(* Logix 5000 project; controller DNP3Outstation 1756-L62 rev 19.11; software revision 19.01; part 2 of 3 *)

ADD_ON_INSTRUCTION PSDNP3CounterControl16   (* revision 1.0, vendor ProSoft Technology Inc *)
// DNP3 Outstation Counter Control
VAR_IN_OUT
   Control : PSDNP3CounterCtrl; {required}
   Counter : INT; {required}
   FrozenCounter : INT; {required}
END_VAR
VAR_OUTPUT
   CurrentCountValue : DINT; {access Read Only, visible}
   FrozenCountValue : DINT; {access Read Only, visible}
   ClearRequestCount : DINT; {visible}
   FreezeRequestCount : DINT; {access Read Only, visible}
END_VAR
VAR_INPUT
   ResetStatistics : BOOL; {required}
END_VAR
VAR_OUTPUT
   FreezeAction : BOOL; {access Read Only, visible}
   ClearAction : BOOL; {access Read Only, visible}
END_VAR
VAR
   FreezeRequestCounter : COUNTER := (PRE := 2100000000); {access None}
   ClearRequestCounter : COUNTER := (PRE := 2100000000); {access None}
END_VAR

ROUTINE Logic   (* ladder *)
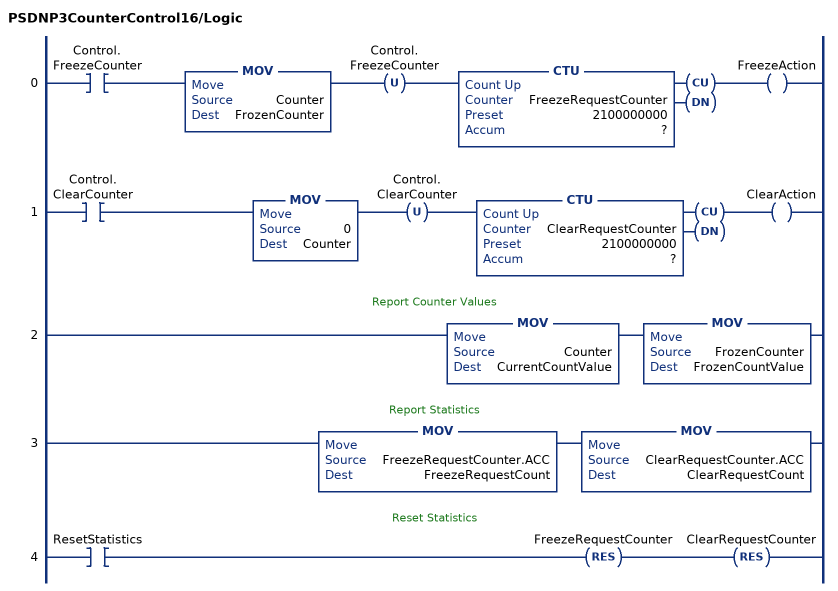
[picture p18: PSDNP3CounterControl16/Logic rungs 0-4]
   0: XIC(Control.FreezeCounter)MOV(Counter,FrozenCounter)OTU(Control.FreezeCounter)CTU(FreezeRequestCounter,?,?)OTE(FreezeAction);
   1: XIC(Control.ClearCounter)MOV(0,Counter)OTU(Control.ClearCounter)CTU(ClearRequestCounter,?,?)OTE(ClearAction);
   // Report Counter Values
   2: MOV(Counter,CurrentCountValue)MOV(FrozenCounter,FrozenCountValue);
   // Report Statistics
   3: MOV(FreezeRequestCounter.ACC,FreezeRequestCount)MOV(ClearRequestCounter.ACC,ClearRequestCount);
   // Reset Statistics
   4: XIC(ResetStatistics)RES(FreezeRequestCounter)RES(ClearRequestCounter);
END_ROUTINE
END_ADD_ON_INSTRUCTION

ADD_ON_INSTRUCTION PSDNP3CounterControl16Flag   (* revision 1.0, vendor ProSoft Technology Inc *)
// DNP3 Outstation Counter Control
VAR_IN_OUT
   Control : PSDNP3CounterCtrl; {required}
   Counter : PSDNP3Counter16WithFlag; {required}
   FrozenCounter : PSDNP3FrozenCounter16WithFlag; {required}
END_VAR
VAR_OUTPUT
   CurrentCountValue : DINT; {access Read Only, visible}
   FrozenCountValue : DINT; {access Read Only, visible}
   ClearRequestCount : DINT; {visible}
   FreezeRequestCount : DINT; {access Read Only, visible}
END_VAR
VAR_INPUT
   ResetStatistics : BOOL; {required}
END_VAR
VAR_OUTPUT
   FreezeAction : BOOL; {access Read Only, visible}
   ClearAction : BOOL; {access Read Only, visible}
END_VAR
VAR
   FreezeRequestCounter : COUNTER := (PRE := 2100000000); {access None}
   ClearRequestCounter : COUNTER := (PRE := 2100000000); {access None}
END_VAR

ROUTINE Logic   (* ladder *)
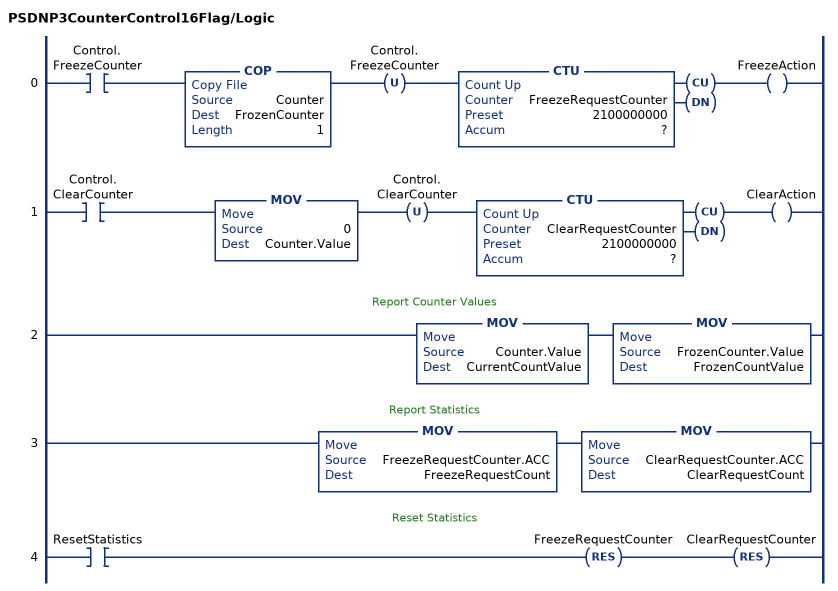
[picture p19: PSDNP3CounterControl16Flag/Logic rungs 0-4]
   0: XIC(Control.FreezeCounter)COP(Counter,FrozenCounter,1)OTU(Control.FreezeCounter)CTU(FreezeRequestCounter,?,?)OTE(FreezeAction);
   1: XIC(Control.ClearCounter)MOV(0,Counter.Value)OTU(Control.ClearCounter)CTU(ClearRequestCounter,?,?)OTE(ClearAction);
   // Report Counter Values
   2: MOV(Counter.Value,CurrentCountValue)MOV(FrozenCounter.Value,FrozenCountValue);
   // Report Statistics
   3: MOV(FreezeRequestCounter.ACC,FreezeRequestCount)MOV(ClearRequestCounter.ACC,ClearRequestCount);
   // Reset Statistics
   4: XIC(ResetStatistics)RES(FreezeRequestCounter)RES(ClearRequestCounter);
END_ROUTINE
END_ADD_ON_INSTRUCTION

ADD_ON_INSTRUCTION PSDNP3CounterControl16FlagTime   (* revision 1.0, vendor ProSoft Technology Inc *)
// DNP3 Outstation Counter Control
VAR_IN_OUT
   Control : PSDNP3CounterCtrl; {required}
   Counter : PSDNP3Counter16WithFlag; {required}
   FrozenCounter : PSDNP3FrozenCounter16WithFlagTimeRev2; {required}
END_VAR
VAR_OUTPUT
   CurrentCountValue : DINT; {access Read Only, visible}
   FrozenCountValue : DINT; {access Read Only, visible}
   ClearRequestCount : DINT; {visible}
   FreezeRequestCount : DINT; {access Read Only, visible}
END_VAR
VAR_INPUT
   ResetStatistics : BOOL; {required}
END_VAR
VAR_OUTPUT
   FreezeAction : BOOL; {access Read Only, visible}
   ClearAction : BOOL; {access Read Only, visible}
END_VAR
VAR
   FreezeRequestCounter : COUNTER := (PRE := 2100000000); {access None}
   ClearRequestCounter : COUNTER := (PRE := 2100000000); {access None}
END_VAR

ROUTINE Logic   (* ladder *)
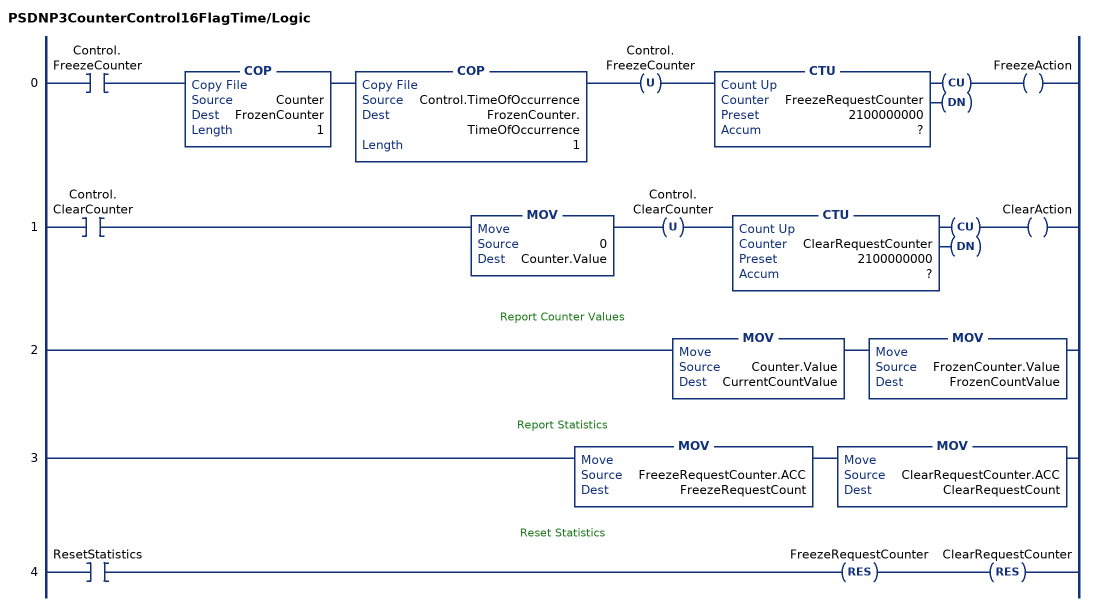
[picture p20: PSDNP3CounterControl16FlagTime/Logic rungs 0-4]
   0: XIC(Control.FreezeCounter)COP(Counter,FrozenCounter,1)COP(Control.TimeOfOccurrence,FrozenCounter.TimeOfOccurrence,1)OTU(Control.FreezeCounter)CTU(FreezeRequestCounter,?,?)OTE(FreezeAction);
   1: XIC(Control.ClearCounter)MOV(0,Counter.Value)OTU(Control.ClearCounter)CTU(ClearRequestCounter,?,?)OTE(ClearAction);
   // Report Counter Values
   2: MOV(Counter.Value,CurrentCountValue)MOV(FrozenCounter.Value,FrozenCountValue);
   // Report Statistics
   3: MOV(FreezeRequestCounter.ACC,FreezeRequestCount)MOV(ClearRequestCounter.ACC,ClearRequestCount);
   // Reset Statistics
   4: XIC(ResetStatistics)RES(FreezeRequestCounter)RES(ClearRequestCounter);
END_ROUTINE
END_ADD_ON_INSTRUCTION

ADD_ON_INSTRUCTION PSDNP3CounterControl32   (* revision 1.0, vendor ProSoft Technology Inc *)
// DNP3 Outstation Counter Control
VAR_IN_OUT
   Control : PSDNP3CounterCtrl; {required}
   Counter : DINT; {required}
   FrozenCounter : DINT; {required}
END_VAR
VAR_OUTPUT
   CurrentCountValue : DINT; {access Read Only, visible}
   FrozenCountValue : DINT; {access Read Only, visible}
   ClearRequestCount : DINT; {visible}
   FreezeRequestCount : DINT; {access Read Only, visible}
END_VAR
VAR_INPUT
   ResetStatistics : BOOL; {required}
END_VAR
VAR_OUTPUT
   FreezeAction : BOOL; {access Read Only, visible}
   ClearAction : BOOL; {access Read Only, visible}
END_VAR
VAR
   FreezeRequestCounter : COUNTER := (PRE := 2100000000); {access None}
   ClearRequestCounter : COUNTER := (PRE := 2100000000); {access None}
END_VAR

ROUTINE Logic   (* ladder *)
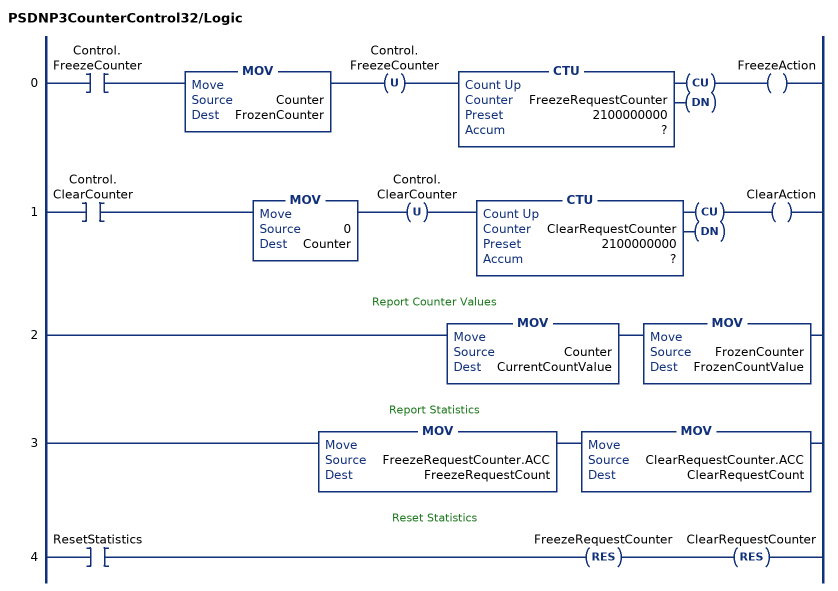
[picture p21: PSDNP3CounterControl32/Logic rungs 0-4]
   0: XIC(Control.FreezeCounter)MOV(Counter,FrozenCounter)OTU(Control.FreezeCounter)CTU(FreezeRequestCounter,?,?)OTE(FreezeAction);
   1: XIC(Control.ClearCounter)MOV(0,Counter)OTU(Control.ClearCounter)CTU(ClearRequestCounter,?,?)OTE(ClearAction);
   // Report Counter Values
   2: MOV(Counter,CurrentCountValue)MOV(FrozenCounter,FrozenCountValue);
   // Report Statistics
   3: MOV(FreezeRequestCounter.ACC,FreezeRequestCount)MOV(ClearRequestCounter.ACC,ClearRequestCount);
   // Reset Statistics
   4: XIC(ResetStatistics)RES(FreezeRequestCounter)RES(ClearRequestCounter);
END_ROUTINE
END_ADD_ON_INSTRUCTION

ADD_ON_INSTRUCTION PSDNP3CounterControl32Flag   (* revision 1.0, vendor ProSoft Technology Inc *)
// DNP3 Outstation Counter Control
VAR_IN_OUT
   Control : PSDNP3CounterCtrl; {required}
   Counter : PSDNP3Counter32WithFlag; {required}
   FrozenCounter : PSDNP3FrozenCounter32WithFlag; {required}
END_VAR
VAR_OUTPUT
   CurrentCountValue : DINT; {access Read Only, visible}
   FrozenCountValue : DINT; {access Read Only, visible}
   ClearRequestCount : DINT; {visible}
   FreezeRequestCount : DINT; {access Read Only, visible}
END_VAR
VAR_INPUT
   ResetStatistics : BOOL; {required}
END_VAR
VAR_OUTPUT
   FreezeAction : BOOL; {access Read Only, visible}
   ClearAction : BOOL; {access Read Only, visible}
END_VAR
VAR
   FreezeRequestCounter : COUNTER := (PRE := 2100000000); {access None}
   ClearRequestCounter : COUNTER := (PRE := 2100000000); {access None}
END_VAR

ROUTINE Logic   (* ladder *)
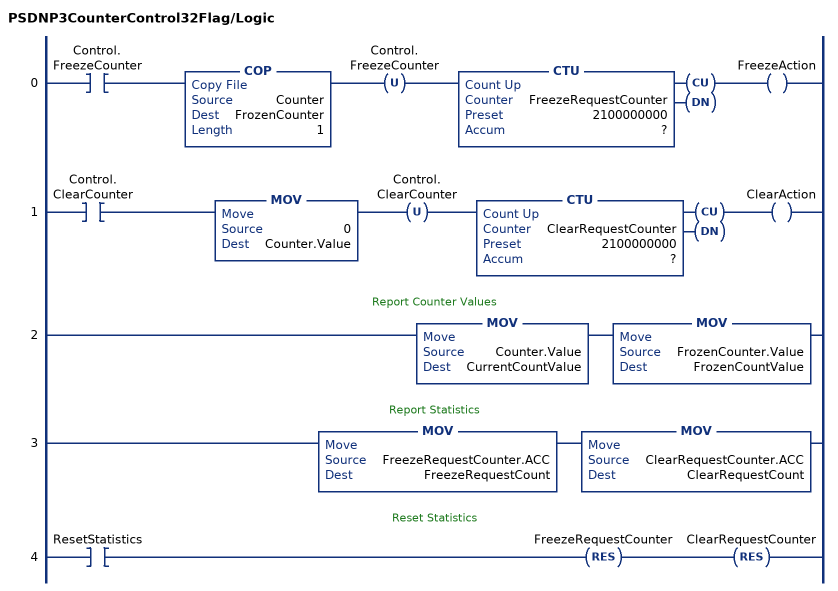
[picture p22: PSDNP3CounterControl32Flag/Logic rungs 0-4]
   0: XIC(Control.FreezeCounter)COP(Counter,FrozenCounter,1)OTU(Control.FreezeCounter)CTU(FreezeRequestCounter,?,?)OTE(FreezeAction);
   1: XIC(Control.ClearCounter)MOV(0,Counter.Value)OTU(Control.ClearCounter)CTU(ClearRequestCounter,?,?)OTE(ClearAction);
   // Report Counter Values
   2: MOV(Counter.Value,CurrentCountValue)MOV(FrozenCounter.Value,FrozenCountValue);
   // Report Statistics
   3: MOV(FreezeRequestCounter.ACC,FreezeRequestCount)MOV(ClearRequestCounter.ACC,ClearRequestCount);
   // Reset Statistics
   4: XIC(ResetStatistics)RES(FreezeRequestCounter)RES(ClearRequestCounter);
END_ROUTINE
END_ADD_ON_INSTRUCTION

ADD_ON_INSTRUCTION PSDNP3CounterControl32FlagTime   (* revision 1.0, vendor ProSoft Technology Inc *)
// DNP3 Outstation Counter Control
VAR_IN_OUT
   Control : PSDNP3CounterCtrl; {required}
   Counter : PSDNP3Counter32WithFlag; {required}
   FrozenCounter : PSDNP3FrozenCounter32WithFlagTime; {required}
END_VAR
VAR_OUTPUT
   CurrentCountValue : DINT; {access Read Only, visible}
   FrozenCountValue : DINT; {access Read Only, visible}
   ClearRequestCount : DINT; {visible}
   FreezeRequestCount : DINT; {access Read Only, visible}
END_VAR
VAR_INPUT
   ResetStatistics : BOOL; {required}
END_VAR
VAR_OUTPUT
   FreezeAction : BOOL; {access Read Only, visible}
   ClearAction : BOOL; {access Read Only, visible}
END_VAR
VAR
   FreezeRequestCounter : COUNTER; {access None}
   ClearRequestCounter : COUNTER; {access None}
END_VAR

ROUTINE Logic   (* ladder *)
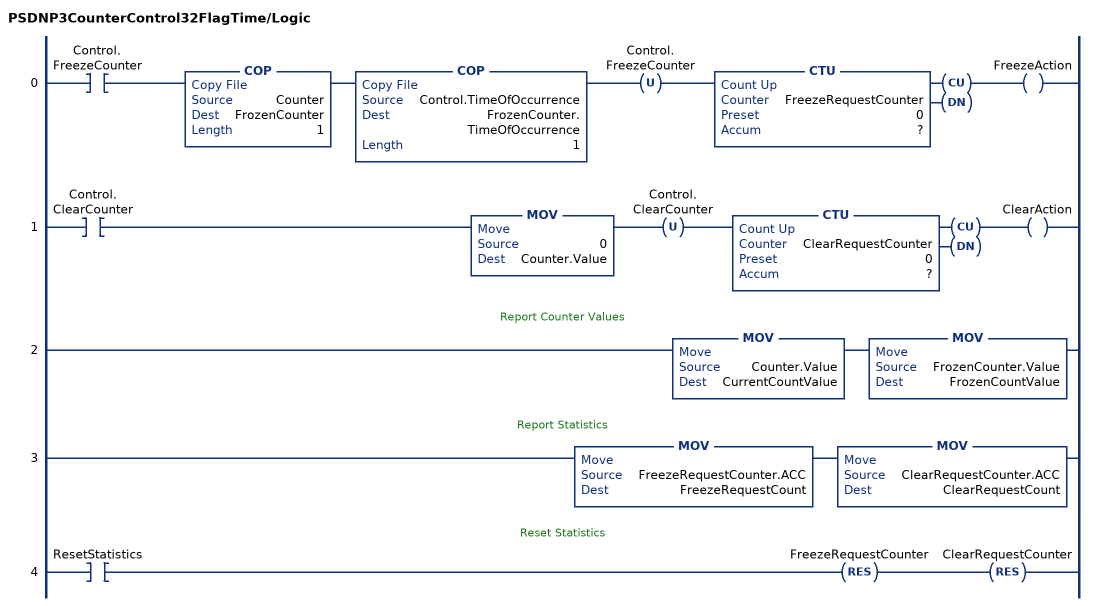
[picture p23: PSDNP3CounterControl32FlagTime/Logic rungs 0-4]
   0: XIC(Control.FreezeCounter)COP(Counter,FrozenCounter,1)COP(Control.TimeOfOccurrence,FrozenCounter.TimeOfOccurrence,1)OTU(Control.FreezeCounter)CTU(FreezeRequestCounter,?,?)OTE(FreezeAction);
   1: XIC(Control.ClearCounter)MOV(0,Counter.Value)OTU(Control.ClearCounter)CTU(ClearRequestCounter,?,?)OTE(ClearAction);
   // Report Counter Values
   2: MOV(Counter.Value,CurrentCountValue)MOV(FrozenCounter.Value,FrozenCountValue);
   // Report Statistics
   3: MOV(FreezeRequestCounter.ACC,FreezeRequestCount)MOV(ClearRequestCounter.ACC,ClearRequestCount);
   // Reset Statistics
   4: XIC(ResetStatistics)RES(FreezeRequestCounter)RES(ClearRequestCounter);
END_ROUTINE
END_ADD_ON_INSTRUCTION

ADD_ON_INSTRUCTION PSDNP3CounterEvtLog16   (* revision 1.0, vendor ProSoft Technology Inc *)
VAR_IN_OUT
   DNP3Object : PSDNP3Counter16WithFlag; {required}
END_VAR
VAR_INPUT
   Deadband : INT; {required}
   MinimumLogInterval : REAL; {required}
   ExtrernalEventTrigger : BOOL; {visible}
END_VAR
VAR_OUTPUT
   EventTriggers : DINT; {access Read Only, visible}
END_VAR
VAR
   RequestLog : BOOL; {access None}
   ExternalONS : BOOL; {access None}
   Interval : TIMER := (PRE := 1000000); {access None}
   PreviousValue : INT; {access None}
   DBRequest : BOOL; {access None}
   ExtRequest : BOOL; {access None}
   Pending : BOOL; {access None}
END_VAR

ROUTINE Logic   (* ladder *)
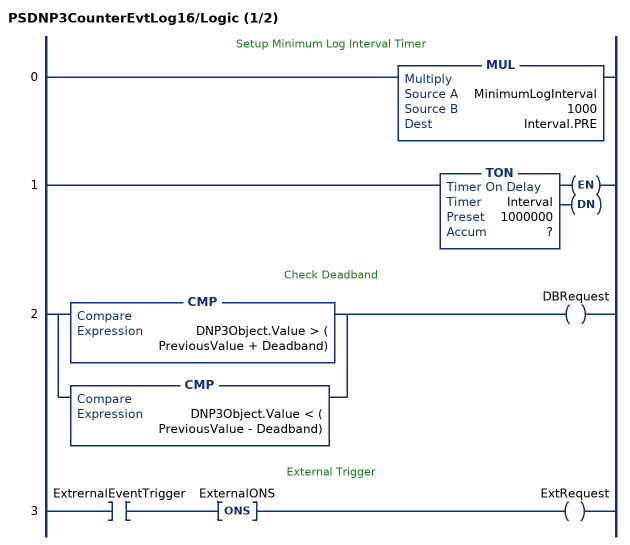
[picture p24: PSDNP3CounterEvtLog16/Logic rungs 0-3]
   // Setup Minimum Log Interval Timer
   0: MUL(MinimumLogInterval,1000,Interval.PRE);
   1: TON(Interval,?,?);
   // Check Deadband
   2: [CMP(DNP3Object.Value > ( PreviousValue + Deadband)) ,CMP(DNP3Object.Value < ( PreviousValue - Deadband)) ]OTE(DBRequest);
   // External Trigger
   3: XIC(ExtrernalEventTrigger)ONS(ExternalONS)OTE(ExtRequest);
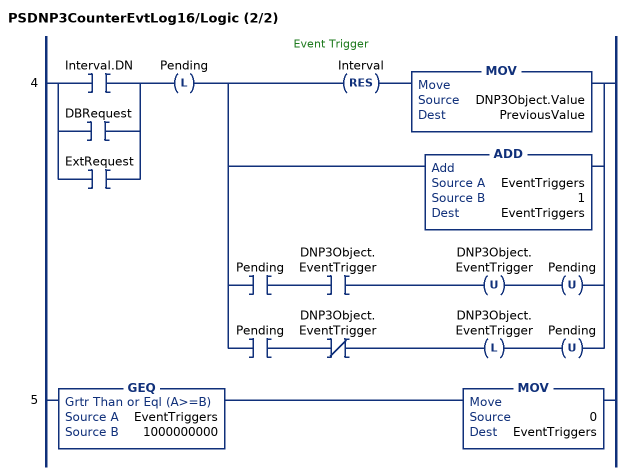
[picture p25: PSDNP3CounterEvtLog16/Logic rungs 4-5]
   // Event Trigger
   4: [XIC(Interval.DN) ,XIC(DBRequest) ,XIC(ExtRequest) ]OTL(Pending)[RES(Interval) MOV(DNP3Object.Value,PreviousValue) ,ADD(EventTriggers,1,EventTriggers) ,XIC(Pending) XIC(DNP3Object.EventTrigger) OTU(DNP3Object.EventTrigger) OTU(Pending) ,XIC(Pending) XIO(DNP3Object.EventTrigger) OTL(DNP3Object.EventTrigger) OTU(Pending) ];
   5: GEQ(EventTriggers,1000000000)MOV(0,EventTriggers);
END_ROUTINE
END_ADD_ON_INSTRUCTION

ADD_ON_INSTRUCTION PSDNP3CounterEvtLog32   (* revision 1.0, vendor ProSoft Technology Inc *)
VAR_IN_OUT
   DNP3Object : PSDNP3Counter32WithFlag; {required}
END_VAR
VAR_INPUT
   Deadband : DINT; {required}
   MinimumLogInterval : REAL; {required}
   ExtrernalEventTrigger : BOOL; {visible}
END_VAR
VAR_OUTPUT
   EventTriggers : DINT; {access Read Only, visible}
END_VAR
VAR
   RequestLog : BOOL; {access None}
   ExternalONS : BOOL; {access None}
   Interval : TIMER := (PRE := 1000000); {access None}
   PreviousValue : DINT; {access None}
   DBRequest : BOOL; {access None}
   ExtRequest : BOOL; {access None}
   Pending : BOOL; {access None}
END_VAR

ROUTINE Logic   (* ladder *)
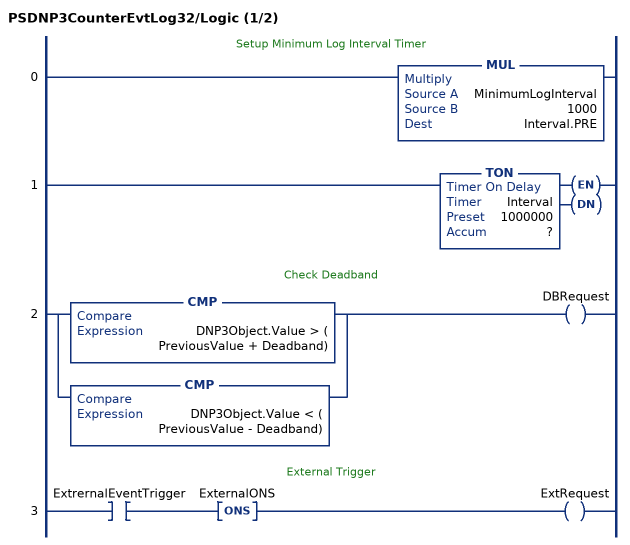
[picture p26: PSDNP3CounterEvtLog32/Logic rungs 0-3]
   // Setup Minimum Log Interval Timer
   0: MUL(MinimumLogInterval,1000,Interval.PRE);
   1: TON(Interval,?,?);
   // Check Deadband
   2: [CMP(DNP3Object.Value > ( PreviousValue + Deadband)) ,CMP(DNP3Object.Value < ( PreviousValue - Deadband)) ]OTE(DBRequest);
   // External Trigger
   3: XIC(ExtrernalEventTrigger)ONS(ExternalONS)OTE(ExtRequest);
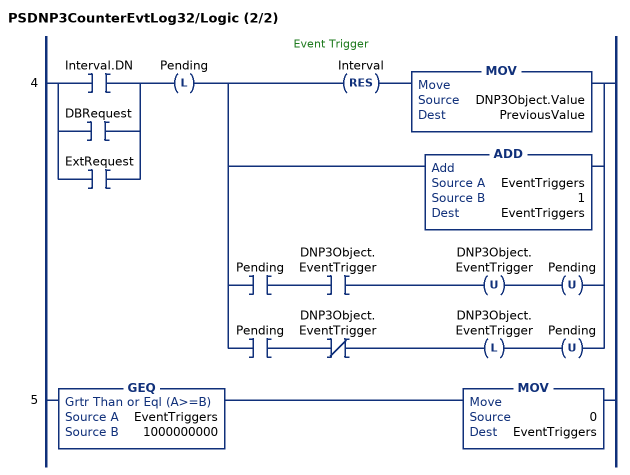
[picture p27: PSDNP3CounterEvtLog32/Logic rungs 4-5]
   // Event Trigger
   4: [XIC(Interval.DN) ,XIC(DBRequest) ,XIC(ExtRequest) ]OTL(Pending)[RES(Interval) MOV(DNP3Object.Value,PreviousValue) ,ADD(EventTriggers,1,EventTriggers) ,XIC(Pending) XIC(DNP3Object.EventTrigger) OTU(DNP3Object.EventTrigger) OTU(Pending) ,XIC(Pending) XIO(DNP3Object.EventTrigger) OTL(DNP3Object.EventTrigger) OTU(Pending) ];
   5: GEQ(EventTriggers,1000000000)MOV(0,EventTriggers);
END_ROUTINE
END_ADD_ON_INSTRUCTION

VAR_GLOBAL   (* controller tags *)
   DNP3AnalogOutputRealControl00 : PSDNP3AnalogOutputRealControl := (RequestCount := 37);
   DNP3AnalogOutputRealControl01 : PSDNP3AnalogOutputRealControl := (CurrentOutput := 760.0);
   DNP3BinaryOutputCROB00 : PSDNP3BinaryOutputCROBWithFlag := (CurrentState := 1, LatchOnRequestCount := 1, LatchOffRequestCount := 1, CurrentPulseTarget := 100);
   DNP3BinaryOutputCROB01 : PSDNP3BinaryOutputCROBWithFlag := (CurrentPulseTarget := 100);
   DNP3CounterControl32FlagTime00 : PSDNP3CounterControl32FlagTime := (CurrentCountValue := 17, FrozenCountValue := 95);
   DNP3CounterControl32FlagTime01 : PSDNP3CounterControl32FlagTime := (CurrentCountValue := 11, FrozenCountValue := 124);
   DNP3G01V01 : PSDNP3BinaryInputPacked[10] := ([0].BinaryValues[0] := 9, [0].BinaryValues[1] := 1, [0].BinaryValues[2] := 1, [0].BinaryValues[3] := -64);
   DNP3G01V02 : PSDNP3BinaryInputWithFlag[100];
   DNP3G03V01 : PSDNP3DoubleBinaryInputPacked[10];
   DNP3G03V02 : PSDNP3DoubleBinaryInputWithFlag[10] := ([0].Online := 1, [0].LocalForced := 1, [0].State0 := 1, [0].State1 := 1, [1].Online := 1, [1].State1 := 1);
   DNP3G10V01 : PSDNP3BinaryOutputPacked[10];
   DNP3G10V02 : PSDNP3BinaryOutputWithFlag[10] := ([0].Online := 1, [0].LocalForced := 1, [0].Reserved2 := 1, [0].State := 1, [1].Online := 1, [1].Restart := 1);
   DNP3G110V01 : STRING[10];
   DNP3G12V01 : PSDNP3CROB[10] := ([3].RequestPending := 1, [3].ControlCode := 3, [3].Count := 1, [3].OnTime := 100, [3].OffTime := 100);
   DNP3G20V01 : PSDNP3Counter32WithFlag[10];
   DNP3G20V01AnalogInputEvtLog00 : PSDNP3CounterEvtLog32;
   DNP3G20V01Ctrl : PSDNP3CounterCtrl[10];
   DNP3G20V02 : PSDNP3Counter16WithFlag[10];
   DNP3G20V02Ctrl : PSDNP3CounterCtrl[10];
   DNP3G20V05 : DINT[10] := ([0] := 143, [1] := 144, [2] := 145, [3] := 146, [4] := 147, [5] := 148, [6] := 149, [7] := 150, [8] := 151, [9] := 152);
   DNP3G20V05Ctrl : PSDNP3CounterCtrl[10];
   DNP3G20V06 : INT[10] := ([0] := 6, [1] := 154, [2] := 155, [3] := 156, [4] := 157, [5] := 158, [6] := 159, [7] := 160, [8] := 161, [9] := 162);
   DNP3G20V06Ctrl : PSDNP3CounterCtrl[10];
   DNP3G21V01 : PSDNP3FrozenCounter32WithFlag[10] := ([0].LocalForced := 1, [0].Value := 88, [1].Online := 1, [1].Value := 324, [2].Restart := 1, [2].CommLost := 1, [2].Value := 100268, [9].Online := 1, [9].Value := 123456789);
   DNP3G21V02 : PSDNP3FrozenCounter16WithFlag[10] := ([0].Online := 1, [0].Value := 32000, [5].Restart := 1, [5].CommLost := 1, [5].Value := 31000);
   DNP3G21V05 : PSDNP3FrozenCounter32WithFlagTime[100];
   DNP3G21V06 : PSDNP3FrozenCounter16WithFlagTimeRev2[10] := ([0].Online := 1, [0].Value := 3);
   DNP3G21V09 : DINT[10];
   DNP3G21V10 : INT[10] := ([0] := 6);
   DNP3G30V01 : PSDNP3AnalogInput32Flag[10];
   DNP3G30V02 : PSDNP3AnalogInput16Flag[10];
   DNP3G30V03 : DINT[200];
   DNP3G30V04 : INT[10];
   DNP3G30V05 : PSDNP3AnalogInputRealFlag[100];
   DNP3G30V05AnalogInputEvtLog00 : PSDNP3AnalogInputEvtLogReal := (Deadband := 12.0, MinimumLogInterval := 120.0, EventTriggers := 26);
   DNP3G40V01 : PSDNP3AnalogOutputStatus32Flag[10] := ([0].Online := 1, [0].Value := 56, [9].Online := 1, [9].Value := 1512);
   DNP3G40V02 : PSDNP3AnalogOutputStatus16Flag[10] := ([0].Online := 1, [0].Value := 123, [9].Value := 667);
   DNP3G40V03 : PSDNP3AnalogOutputStatusRealFlag[10] := ([0].Online := 1, [1].Online := 1, [1].Value := 760.0, [9].Online := 1, [9].Value := 234.654);
   DNP3G40V03AnalogOutputStatusEvtLog00 : PSDNP3AnalogOutputStatusEvtLogReal;
   DNP3G41V01 : PSDNP3AnalogOutput32[10] := ([0].Value := 56, [7].RequestPending := 1, [7].Value := 77);
   DNP3G41V02 : PSDNP3AnalogOutput16[10] := ([0].Value := 123);
   DNP3G41V03 : PSDNP3AnalogOutputReal[10];
   DNP3ResetStatistics : BOOL;
   DNP3ResetStatisticsRequest : BOOL;
   DNP3TimeNeeded : SINT := 1;
   DNP3TimeNeededMsg : MESSAGE;
        MessageParameters(ServiceCode := 16#0010, LocalElement := DNP3TimeNeeded, ...)
   DummyAnalogInput00 : REAL := 420.0;
   DummyAnalogInput01 : REAL := 25.7;
   DummyAnalogOutput00 : REAL;
   DummyAnalogOutput01 : REAL := 760.0;
   DummyBinaryInput00 : BOOL;
   DummyBinaryInput01 : BOOL;
   DummyCounter00 : COUNTER := (PRE := 123);
   DummyCounter01 : COUNTER := (PRE := 123);
   DummyCounterPulse00 : BOOL := 1;
   DummyCounterPulse01 : BOOL := 1;
   DummyDoubleBinaryInput00_0 : BOOL := 1;
   DummyDoubleBinaryInput00_1 : BOOL := 1;
   DummyDoubleBinaryInput01_0 : BOOL;
   DummyDoubleBinaryInput01_1 : BOOL := 1;
   DummyOutput00 : BOOL := 1;
   DummyOutput01 : BOOL;
   PLX51DNPSInput : PLX51DNPInput;
   PLX51DNPSOutput : PLX51DNPOutput;
   SetDNP3TimeNeeded : BOOL;
   ShiftCounter : PSDNP3Counter32WithFlag[10];
   ShiftCounterCtrl : PSDNP3CounterCtrl[10];
END_VAR

PROGRAM DNP3Outstation   (* main routine MainRoutine *)

ROUTINE AnalogInputs   (* ladder *)
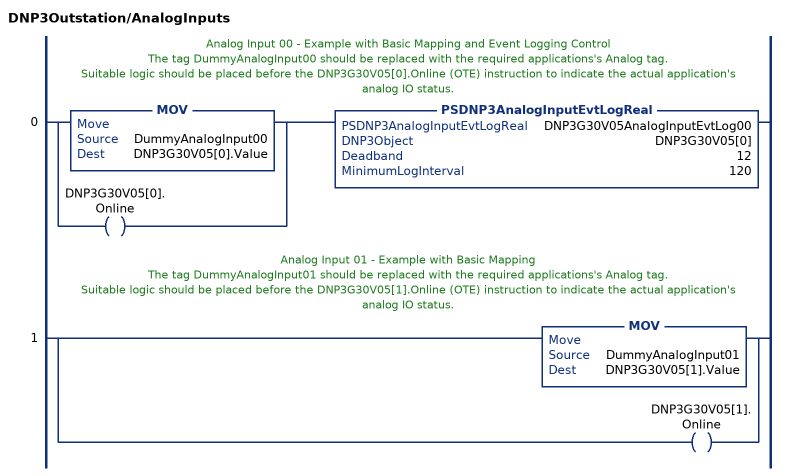
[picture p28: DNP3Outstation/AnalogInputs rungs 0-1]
   // Analog Input 00 - Example with Basic Mapping and Event Logging Control
   // The tag DummyAnalogInput00 should be replaced with the required applications's Analog tag.
   // Suitable logic should be placed before the DNP3G30V05[0].Online (OTE) instruction to indicate the actual application's analog IO status.
   0: [MOV(DummyAnalogInput00,DNP3G30V05[0].Value) ,OTE(DNP3G30V05[0].Online) ]PSDNP3AnalogInputEvtLogReal(DNP3G30V05AnalogInputEvtLog00,DNP3G30V05[0],12,120);
   // Analog Input 01 - Example with Basic Mapping
   // The tag DummyAnalogInput01 should be replaced with the required applications's Analog tag.
   // Suitable logic should be placed before the DNP3G30V05[1].Online (OTE) instruction to indicate the actual application's analog IO status.
   1: [MOV(DummyAnalogInput01,DNP3G30V05[1].Value) ,OTE(DNP3G30V05[1].Online) ];
END_ROUTINE

ROUTINE AnalogOutputs   (* ladder *)
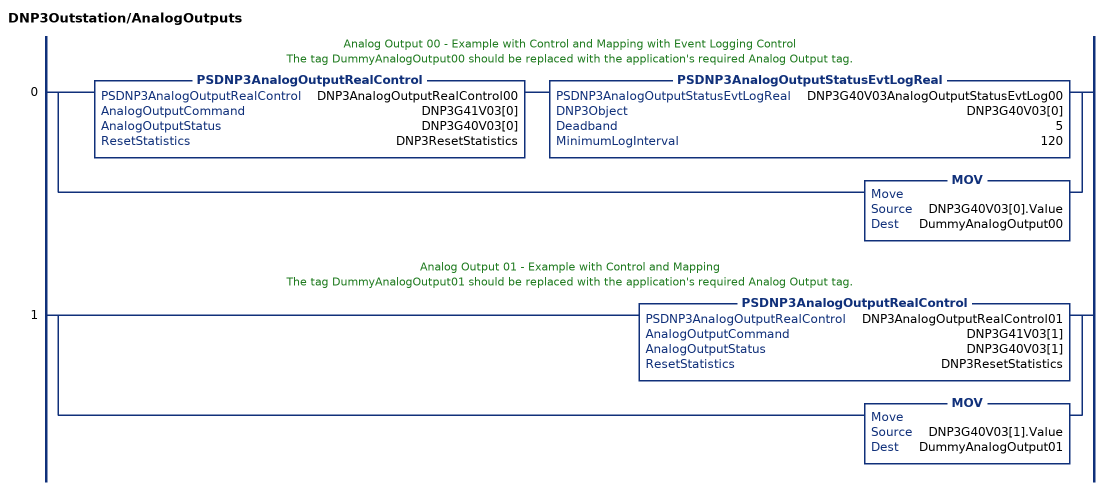
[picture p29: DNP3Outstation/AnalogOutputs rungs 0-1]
   // Analog Output 00 - Example with Control and Mapping with Event Logging Control
   // The tag DummyAnalogOutput00 should be replaced with the application's required Analog Output tag.
   0: [PSDNP3AnalogOutputRealControl(DNP3AnalogOutputRealControl00,DNP3G41V03[0],DNP3G40V03[0],DNP3ResetStatistics) PSDNP3AnalogOutputStatusEvtLogReal(DNP3G40V03AnalogOutputStatusEvtLog00,DNP3G40V03[0],5,120) ,MOV(DNP3G40V03[0].Value,DummyAnalogOutput00) ];
   // Analog Output 01 - Example with Control and Mapping
   // The tag DummyAnalogOutput01 should be replaced with the application's required Analog Output tag.
   1: [PSDNP3AnalogOutputRealControl(DNP3AnalogOutputRealControl01,DNP3G41V03[1],DNP3G40V03[1],DNP3ResetStatistics) ,MOV(DNP3G40V03[1].Value,DummyAnalogOutput01) ];
END_ROUTINE

ROUTINE BinaryInputs   (* ladder *)
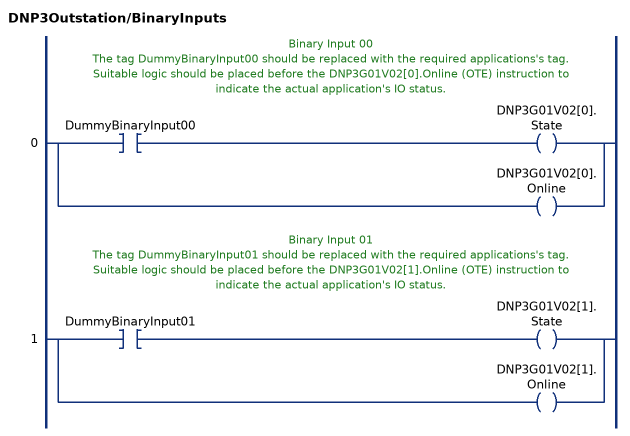
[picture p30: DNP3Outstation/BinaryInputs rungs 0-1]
   // Binary Input 00
   // The tag DummyBinaryInput00 should be replaced with the required applications's tag.
   // Suitable logic should be placed before the DNP3G01V02[0].Online (OTE) instruction to indicate the actual application's IO status.
   0: [XIC(DummyBinaryInput00) OTE(DNP3G01V02[0].State) ,OTE(DNP3G01V02[0].Online) ];
   // Binary Input 01
   // The tag DummyBinaryInput01 should be replaced with the required applications's tag.
   // Suitable logic should be placed before the DNP3G01V02[1].Online (OTE) instruction to indicate the actual application's IO status.
   1: [XIC(DummyBinaryInput01) OTE(DNP3G01V02[1].State) ,OTE(DNP3G01V02[1].Online) ];
END_ROUTINE

ROUTINE BinaryOutputs   (* ladder *)
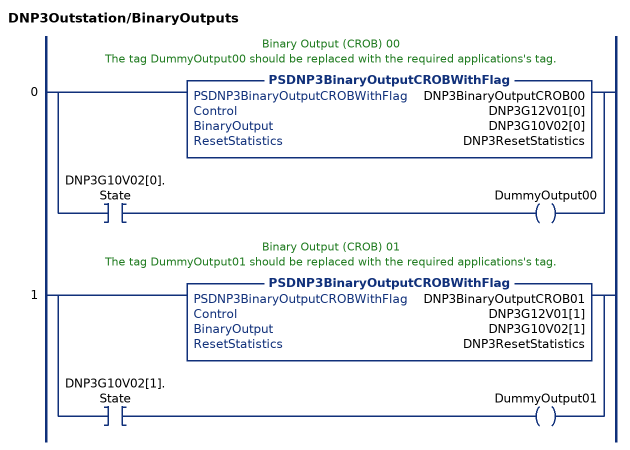
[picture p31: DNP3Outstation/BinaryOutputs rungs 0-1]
   // Binary Output (CROB) 00
   // The tag DummyOutput00 should be replaced with the required applications's tag.
   0: [PSDNP3BinaryOutputCROBWithFlag(DNP3BinaryOutputCROB00,DNP3G12V01[0],DNP3G10V02[0],DNP3ResetStatistics) ,XIC(DNP3G10V02[0].State) OTE(DummyOutput00) ];
   // Binary Output (CROB) 01
   // The tag DummyOutput01 should be replaced with the required applications's tag.
   1: [PSDNP3BinaryOutputCROBWithFlag(DNP3BinaryOutputCROB01,DNP3G12V01[1],DNP3G10V02[1],DNP3ResetStatistics) ,XIC(DNP3G10V02[1].State) OTE(DummyOutput01) ];
END_ROUTINE

ROUTINE Counters   (* ladder *)
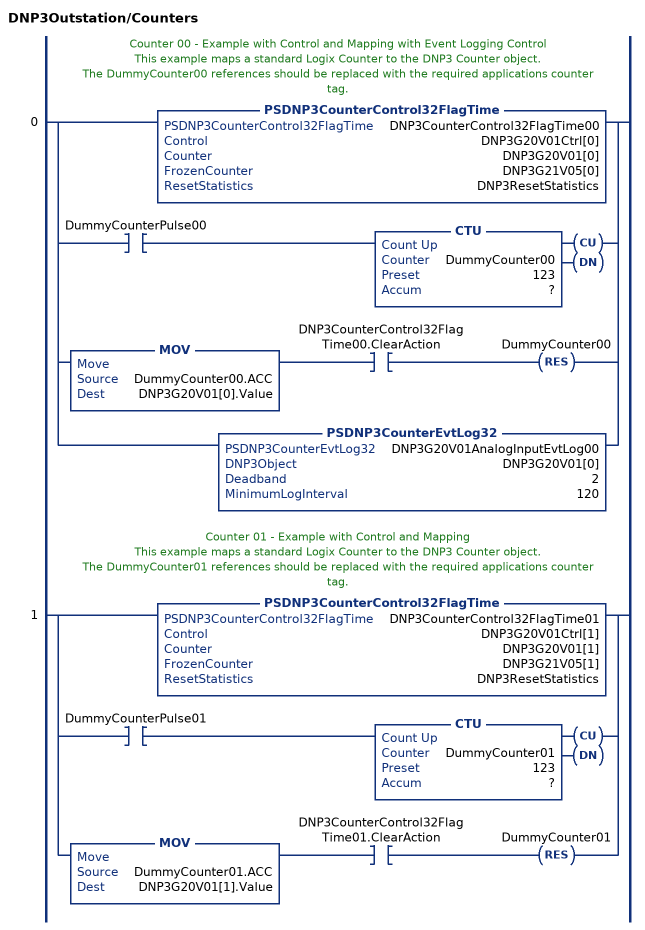
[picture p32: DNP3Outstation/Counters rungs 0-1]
   // Counter 00 - Example with Control and Mapping with Event Logging Control
   // This example maps a standard Logix Counter to the DNP3 Counter object.
   // The DummyCounter00 references should be replaced with the required applications counter tag.
   0: [PSDNP3CounterControl32FlagTime(DNP3CounterControl32FlagTime00,DNP3G20V01Ctrl[0],DNP3G20V01[0],DNP3G21V05[0],DNP3ResetStatistics) ,XIC(DummyCounterPulse00) CTU(DummyCounter00,?,?) ,MOV(DummyCounter00.ACC,DNP3G20V01[0].Value) XIC(DNP3CounterControl32FlagTime00.ClearAction) RES(DummyCounter00) ,PSDNP3CounterEvtLog32(DNP3G20V01AnalogInputEvtLog00,DNP3G20V01[0],2,120) ];
   // Counter 01 - Example with Control and Mapping
   // This example maps a standard Logix Counter to the DNP3 Counter object.
   // The DummyCounter01 references should be replaced with the required applications counter tag.
   1: [PSDNP3CounterControl32FlagTime(DNP3CounterControl32FlagTime01,DNP3G20V01Ctrl[1],DNP3G20V01[1],DNP3G21V05[1],DNP3ResetStatistics) ,XIC(DummyCounterPulse01) CTU(DummyCounter01,?,?) ,MOV(DummyCounter01.ACC,DNP3G20V01[1].Value) XIC(DNP3CounterControl32FlagTime01.ClearAction) RES(DummyCounter01) ];
END_ROUTINE

ROUTINE DoubleBinaryInputs   (* ladder *)
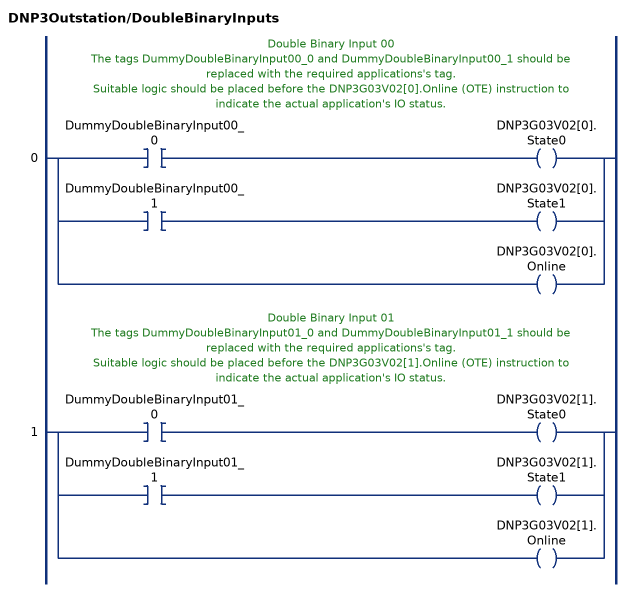
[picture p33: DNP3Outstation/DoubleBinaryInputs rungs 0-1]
   // Double Binary Input 00
   // The tags DummyDoubleBinaryInput00_0 and DummyDoubleBinaryInput00_1 should be replaced with the required applications's tag.
   // Suitable logic should be placed before the DNP3G03V02[0].Online (OTE) instruction to indicate the actual application's IO status.
   0: [XIC(DummyDoubleBinaryInput00_0) OTE(DNP3G03V02[0].State0) ,XIC(DummyDoubleBinaryInput00_1) OTE(DNP3G03V02[0].State1) ,OTE(DNP3G03V02[0].Online) ];
   // Double Binary Input 01
   // The tags DummyDoubleBinaryInput01_0 and DummyDoubleBinaryInput01_1 should be replaced with the required applications's tag.
   // Suitable logic should be placed before the DNP3G03V02[1].Online (OTE) instruction to indicate the actual application's IO status.
   1: [XIC(DummyDoubleBinaryInput01_0) OTE(DNP3G03V02[1].State0) ,XIC(DummyDoubleBinaryInput01_1) OTE(DNP3G03V02[1].State1) ,OTE(DNP3G03V02[1].Online) ];
END_ROUTINE

ROUTINE MainRoutine   (* ladder *)
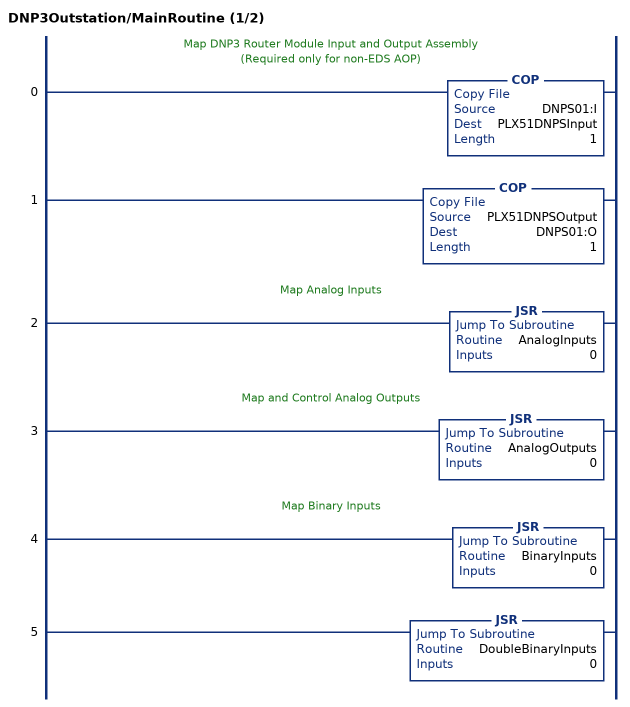
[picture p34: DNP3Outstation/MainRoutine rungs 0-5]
   // Map DNP3 Router Module Input and Output Assembly
   //  (Required only for non-EDS AOP)
   0: COP(DNPS01:I,PLX51DNPSInput,1);
   1: COP(PLX51DNPSOutput,DNPS01:O,1);
   // Map Analog Inputs
   2: JSR(AnalogInputs,0);
   // Map and Control Analog Outputs
   3: JSR(AnalogOutputs,0);
   // Map Binary Inputs
   4: JSR(BinaryInputs,0);
   5: JSR(DoubleBinaryInputs,0);
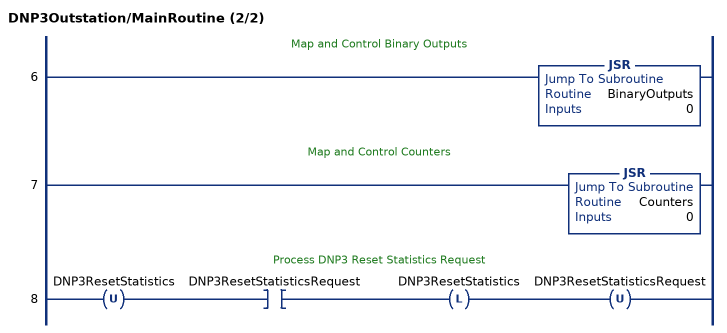
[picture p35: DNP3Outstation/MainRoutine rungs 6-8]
   // Map and Control Binary Outputs
   6: JSR(BinaryOutputs,0);
   // Map and Control Counters
   7: JSR(Counters,0);
   // Process DNP3 Reset Statistics Request
   8: OTU(DNP3ResetStatistics)XIC(DNP3ResetStatisticsRequest)OTL(DNP3ResetStatistics)OTU(DNP3ResetStatisticsRequest);
END_ROUTINE
